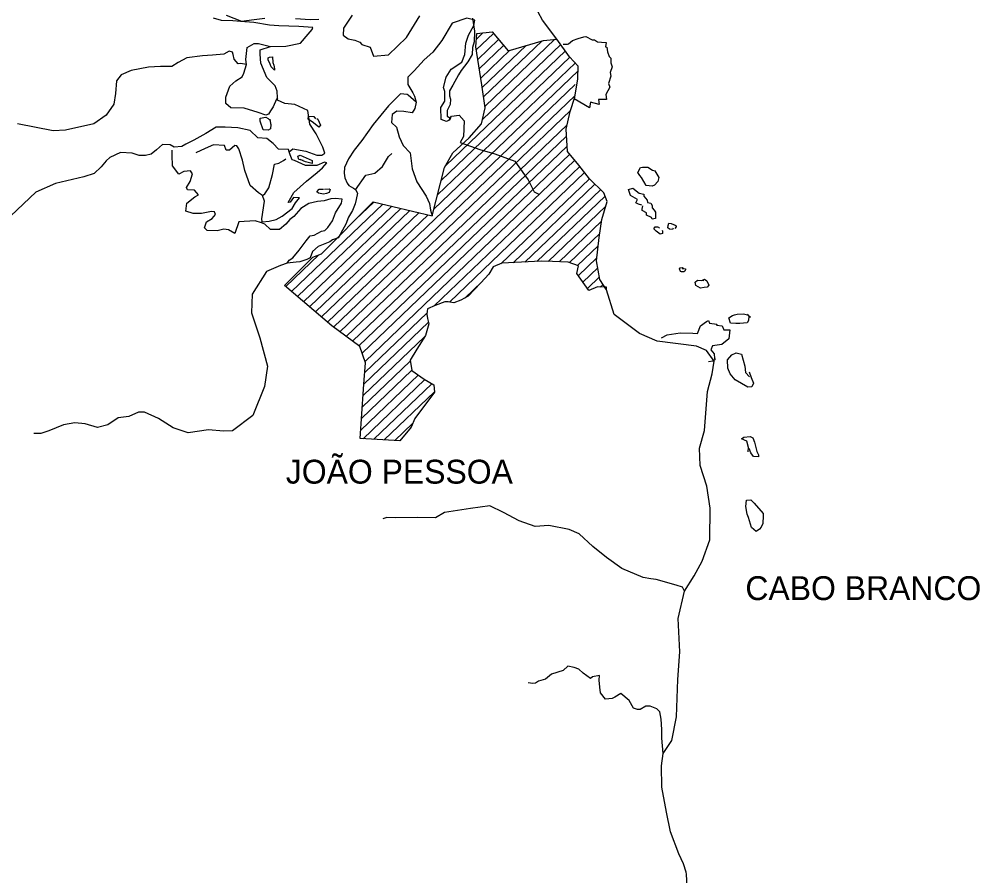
# Model space of a CAD drawing. Extents: x 662444 to 1640468, y 7452018 to 9606170.
# Drawn here: x 1612766 to 1640468, y 9181911 to 9206605 of the extents above; entities that cross this region are included whole.
import ezdxf

# ---------------------------------------------------------------- set-up
doc = ezdxf.new("R2010")
doc.units = 0
doc.layers.add('Level 1', color=7, linetype='Continuous')
doc.layers.add('Level 3', color=7, linetype='Continuous')

msp = doc.modelspace()

# ---------------------------------------------------------------- linework, layer by layer
at = {"layer": 'Level 1'}
for points in [[(1632013, 9181954), (1632000, 9182019), (1631926, 9182258), (1631789, 9182548), (1631550, 9183174), (1631430, 9183749), (1631298, 9184462), (1631293, 9185082), (1631337, 9185439), (1631591, 9185808), (1631718, 9186497), (1631761, 9187573), (1631818, 9188363), (1631767, 9189326), (1631953, 9190120), (1632234, 9190561), (1632458, 9190978), (1632680, 9191600), (1632691, 9192513), (1632598, 9193144), (1632406, 9193737), (1632389, 9194243), (1632526, 9194753), (1632617, 9195868), (1632754, 9196378), (1632806, 9196743), (1632590, 9197059), (1632302, 9197182), (1631164, 9197321), (1630653, 9197547), (1629925, 9198090), (1629704, 9198806), (1629511, 9199105), (1629414, 9199638), (1629491, 9200313), (1629564, 9200833), (1629726, 9201350), (1629628, 9201598), (1629211, 9202002), (1628908, 9202402), (1628580, 9202794), (1628535, 9203440), (1628656, 9203942), (1628789, 9204354), (1628879, 9204890), (1628890, 9205256), (1628639, 9205517), (1628275, 9206033), (1627853, 9206574), (1627478, 9207279)], [(1618739, 9206718), (1619180, 9206551), (1619546, 9206597), (1619847, 9206638)], [(1622368, 9206722), (1622122, 9206345), (1622107, 9206142), (1622257, 9206040), (1622443, 9206003), (1622586, 9205941), (1622650, 9205873), (1622890, 9205802), (1622987, 9205538), (1623417, 9205575), (1623934, 9206074), (1624318, 9206699)], [(1619756, 9200738), (1619773, 9200761), (1619975, 9200788), (1620179, 9200831), (1620352, 9200924), (1620634, 9201153), (1620729, 9201313), (1620846, 9201457), (1620677, 9201462), (1620583, 9201334), (1620518, 9201319), (1620681, 9201608), (1621047, 9201932), (1621362, 9202183), (1621512, 9202318), (1621638, 9202461), (1621574, 9202480), (1621345, 9202388), (1621020, 9202390), (1620701, 9202529), (1620637, 9202555), (1620576, 9202696), (1620547, 9202786), (1620655, 9202873), (1621033, 9202797), (1621346, 9202690), (1621491, 9202686), (1621582, 9202748), (1621522, 9202921), (1621332, 9203301), (1621146, 9203576), (1621093, 9203969), (1620718, 9204150), (1620427, 9204176), (1620219, 9204271), (1620214, 9204337), (1620204, 9204532), (1620143, 9204681), (1619908, 9204924), (1619734, 9205337), (1619718, 9205599), (1619714, 9205720), (1620008, 9205818), (1620453, 9205829), (1620877, 9205916), (1621096, 9206170), (1621213, 9206306), (1621231, 9206371), (1620827, 9206399), (1620253, 9206414), (1619986, 9206438), (1619535, 9206509), (1619147, 9206543), (1618929, 9206558), (1618598, 9206567), (1618373, 9206631)], [(1625838, 9206640), (1625892, 9206264), (1625883, 9205954), (1625838, 9205792), (1625831, 9205588), (1625703, 9205379), (1625509, 9205124), (1625432, 9205003), (1625270, 9204707), (1625175, 9204539), (1625171, 9204392), (1625200, 9204301), (1625196, 9204146), (1625110, 9203969), (1625107, 9203880), (1625105, 9203815), (1625200, 9203755), (1625165, 9203691), (1625091, 9203652), (1624931, 9203714), (1624926, 9204064), (1625045, 9204240), (1625037, 9204518), (1625000, 9204633), (1625083, 9204933), (1625227, 9205165), (1625533, 9205369), (1625620, 9205593), (1625646, 9205912), (1625727, 9206146), (1625873, 9206427), (1625910, 9206581), (1625677, 9206637), (1625252, 9206493), (1624952, 9205988), (1624699, 9205653), (1624442, 9205432), (1624157, 9205121), (1623973, 9204931), (1623970, 9204841), (1623974, 9204719), (1624059, 9204578), (1624121, 9204487), (1624166, 9204388), (1624210, 9204215), (1623981, 9204418), (1623950, 9204434), (1623764, 9204456), (1623413, 9204107), (1622976, 9203573), (1622646, 9203110), (1622427, 9202830), (1622265, 9202582), (1622144, 9202333), (1622140, 9202170), (1622159, 9202031), (1622220, 9201883), (1622274, 9201807), (1622402, 9201738), (1622465, 9201696), (1622518, 9201588), (1622481, 9201410), (1622452, 9201280), (1622382, 9201087), (1622262, 9200902), (1622183, 9200693), (1622089, 9200524), (1622020, 9200396), (1621960, 9200299), (1621796, 9200247), (1621722, 9200192), (1621533, 9200108), (1621386, 9200055), (1621228, 9199912), (1621158, 9199727), (1621059, 9199681), (1620863, 9199614), (1620749, 9199600), (1620497, 9199575), (1620549, 9199663), (1620655, 9199725), (1620841, 9199948), (1621043, 9200212), (1621161, 9200363), (1621274, 9200384), (1621481, 9200493), (1621578, 9200514), (1621670, 9200601), (1621797, 9200794), (1621885, 9201020), (1622064, 9201300), (1622084, 9201422), (1621874, 9201435), (1621752, 9201430), (1621564, 9201370), (1621369, 9201352), (1621116, 9201294)], [(1620737, 9206630), (1621156, 9206593), (1621408, 9206610)], [(1629704, 9198806), (1629706, 9198879), (1629439, 9198888), (1629193, 9198781), (1628844, 9199271), (1628892, 9199498), (1628595, 9199605), (1628150, 9199617), (1627818, 9199627), (1626683, 9199570), (1626437, 9199462), (1626309, 9199254), (1626082, 9199007), (1625899, 9198809), (1625715, 9198619), (1625500, 9198502), (1625303, 9198427), (1625135, 9198455), (1625037, 9198459), (1624759, 9198353), (1624537, 9198253), (1624524, 9198106), (1624545, 9197975), (1624581, 9197820), (1624481, 9197487), (1624234, 9197095), (1624038, 9196775), (1624093, 9196479), (1624442, 9196232), (1624720, 9196062), (1624747, 9195857), (1624172, 9195098), (1624068, 9194841), (1623747, 9194451), (1622600, 9194516), (1622693, 9195940), (1622706, 9196087), (1622757, 9196697), (1622585, 9197174), (1621777, 9197769), (1620412, 9198933), (1621231, 9199749), (1621485, 9199840), (1622972, 9201339), (1624676, 9200940), (1625035, 9202332), (1625275, 9202749), (1625741, 9203185), (1626094, 9203591), (1626205, 9204052), (1626103, 9204716), (1625934, 9205806), (1625963, 9206196), (1626410, 9206240), (1626863, 9205697), (1627884, 9205995), (1628275, 9206033)], [(1625948, 9205719), (1626446, 9206196)], [(1625951, 9206033), (1626140, 9206213)], [(1620214, 9204337), (1620181, 9204305), (1620093, 9204079), (1620016, 9203967), (1619957, 9203871), (1619882, 9203840), (1619658, 9203912), (1619257, 9204038), (1618869, 9204048), (1618720, 9204175), (1618725, 9204354), (1618839, 9204677), (1619014, 9204827), (1619196, 9204944), (1619248, 9205048), (1619320, 9205300), (1619301, 9205447), (1619343, 9205788), (1619540, 9205905), (1619663, 9205901), (1620008, 9205818)], [(1625989, 9205448), (1626590, 9206024)], [(1626032, 9205178), (1626735, 9205851)], [(1626115, 9204636), (1627382, 9205849)], [(1626124, 9203711), (1628384, 9205877)], [(1626157, 9204365), (1627848, 9205985)], [(1626199, 9204095), (1628217, 9206027)], [(1628456, 9205889), (1628578, 9205885), (1628610, 9205893), (1628727, 9205996), (1628882, 9206048), (1629046, 9206101), (1629111, 9206106), (1629286, 9206012), (1629359, 9206010), (1629446, 9205950), (1629560, 9205947), (1629696, 9205935), (1629677, 9205805), (1629717, 9205796), (1629736, 9205664), (1629782, 9205533), (1629829, 9205483), (1629825, 9205345), (1629869, 9205229), (1629807, 9205067), (1629829, 9204960), (1629758, 9204751), (1629795, 9204643), (1629683, 9204434), (1629703, 9204287), (1629468, 9204294), (1629487, 9204147), (1629246, 9204210), (1629209, 9204048), (1628775, 9204309)], [(1619320, 9205300), (1619143, 9205329), (1619078, 9205323), (1618961, 9205457), (1618940, 9205588), (1618918, 9205653), (1618822, 9205680), (1618665, 9205595), (1618341, 9205571), (1618056, 9205547), (1617601, 9205494), (1617347, 9205355), (1617165, 9205246), (1616840, 9205239), (1616492, 9205224), (1615995, 9205124), (1615708, 9205001), (1615573, 9204826), (1615538, 9204468), (1615497, 9204159), (1615269, 9203840), (1614921, 9203589), (1614105, 9203408), (1613749, 9203386), (1612718, 9203586)], [(1625068, 9202390), (1628516, 9205691)], [(1626074, 9204907), (1626915, 9205712)], [(1619948, 9205436), (1619950, 9205494), (1619983, 9205509), (1620072, 9205522), (1620083, 9205359), (1620112, 9205277), (1620126, 9205171), (1620125, 9205138), (1620031, 9205230), (1620001, 9205313), (1619948, 9205436)], [(1624832, 9201541), (1628804, 9205346)], [(1624937, 9201954), (1628648, 9205508)], [(1624725, 9201129), (1628886, 9205114)], [(1621652, 9197876), (1628803, 9204723)], [(1621827, 9197731), (1628799, 9204408)], [(1624210, 9204215), (1624172, 9204036), (1624103, 9203909), (1623854, 9203948), (1623660, 9203953), (1623519, 9203860), (1623503, 9203632), (1623645, 9203497), (1623725, 9203217), (1623840, 9202962), (1624036, 9202752), (1624102, 9202294), (1624236, 9201914), (1624500, 9201500), (1624598, 9201293), (1624624, 9201096), (1624674, 9200940)], [(1622010, 9197597), (1628665, 9203969)], [(1619993, 9203723), (1620013, 9203600), (1620020, 9203567), (1620016, 9203445), (1619942, 9203406), (1619806, 9203418), (1619716, 9203666), (1619718, 9203756), (1619881, 9203784), (1619944, 9203741), (1620000, 9203682)], [(1621345, 9203741), (1621377, 9203725), (1621453, 9203551), (1621410, 9203495), (1621253, 9203614), (1621101, 9203724), (1621104, 9203806), (1621258, 9203802), (1621312, 9203734)], [(1625165, 9203691), (1625234, 9203811), (1625453, 9203837), (1625595, 9203678), (1625580, 9203222), (1625487, 9203054), (1626054, 9202850), (1626480, 9202724), (1627057, 9202511), (1627336, 9202120), (1627445, 9201978), (1627621, 9201630), (1627756, 9201561)], [(1620547, 9202786), (1620532, 9202852), (1620241, 9202859), (1620093, 9203019), (1619911, 9203171), (1619645, 9203187), (1619424, 9203396), (1619070, 9203472), (1618707, 9203491), (1618448, 9203489), (1618150, 9203311), (1617805, 9203116), (1617574, 9203001), (1617451, 9202939), (1617239, 9202921), (1617120, 9202981), (1616902, 9202996), (1616727, 9202837), (1616570, 9202711), (1616406, 9202675), (1616228, 9202680), (1616027, 9202743), (1615688, 9202761), (1615377, 9202623), (1615269, 9202519), (1615134, 9202352), (1614925, 9202154), (1614631, 9202064), (1613815, 9201867), (1613241, 9201615), (1612524, 9200934)], [(1622195, 9197462), (1628564, 9203563)], [(1622378, 9197327), (1628549, 9203237)], [(1621116, 9201294), (1620885, 9201145), (1620684, 9200915), (1620568, 9200829), (1620459, 9200701), (1620276, 9200543), (1620008, 9200542), (1619851, 9200694), (1619756, 9200738), (1619571, 9200791), (1619101, 9200764), (1618985, 9200424), (1618802, 9200536), (1618665, 9200556), (1618477, 9200504), (1618186, 9200513), (1618108, 9200589), (1618170, 9200766), (1618326, 9200859), (1618427, 9200979), (1618397, 9201053), (1618308, 9201064), (1618023, 9201007), (1617781, 9201006), (1617572, 9201069), (1617603, 9201304), (1617835, 9201485), (1617935, 9201547), (1617824, 9201673), (1617623, 9201686), (1617593, 9201752), (1617695, 9201929), (1617759, 9202147), (1617704, 9202238), (1617510, 9202212), (1617369, 9202142), (1617190, 9202375), (1617176, 9202685), (1617180, 9202832)], [(1619773, 9200761), (1619767, 9200851), (1619839, 9201362), (1619780, 9201520), (1619668, 9201596), (1619424, 9201815), (1619275, 9202243), (1619203, 9202539), (1619100, 9202868), (1619038, 9202959), (1618981, 9202961), (1618831, 9202826), (1618735, 9202830), (1618682, 9202961), (1618367, 9202986), (1618129, 9202879), (1617858, 9202756)], [(1622561, 9197192), (1628570, 9202946)], [(1619780, 9201520), (1619846, 9201574), (1619964, 9201742), (1620066, 9202131), (1620130, 9202423), (1620253, 9202451), (1620385, 9202529), (1620451, 9202576)], [(1620952, 9202529), (1620831, 9202558), (1620802, 9202656), (1620868, 9202687), (1621219, 9202530), (1621217, 9202449), (1621024, 9202495), (1620871, 9202557)], [(1622468, 9201689), (1622761, 9202112), (1623021, 9202169), (1623247, 9202359), (1623417, 9202648), (1623508, 9202735)], [(1622657, 9196973), (1628649, 9202712)], [(1622741, 9196742), (1628793, 9202539)], [(1624736, 9198343), (1628936, 9202364)], [(1630663, 9202099), (1630602, 9202182), (1630679, 9202334), (1630737, 9202341), (1630898, 9202336), (1631025, 9202251), (1631098, 9202233), (1631212, 9202042), (1631185, 9201929), (1631085, 9201825), (1631020, 9201794), (1630849, 9201808), (1630711, 9202040), (1630663, 9202099)], [(1625171, 9198449), (1629072, 9202185)], [(1626653, 9199557), (1629209, 9202004)], [(1621574, 9201705), (1621704, 9201718), (1621737, 9201700), (1621709, 9201611), (1621627, 9201581), (1621537, 9201560), (1621401, 9201587), (1621346, 9201630), (1621413, 9201709), (1621543, 9201705)], [(1627009, 9199586), (1629370, 9201848)], [(1627351, 9199603), (1629532, 9201691)], [(1630719, 9201248), (1630622, 9201276), (1630551, 9201310), (1630595, 9201407), (1630395, 9201519), (1630336, 9201700), (1630466, 9201737), (1630648, 9201594), (1630776, 9201557), (1630775, 9201500), (1630877, 9201391), (1630883, 9201318), (1630980, 9201306), (1631018, 9201231), (1631024, 9201166), (1631078, 9201100), (1631117, 9201042), (1631113, 9200919), (1631112, 9200862), (1631022, 9200840), (1630999, 9200890), (1630855, 9200959), (1630858, 9201025), (1630730, 9201093), (1630731, 9201126), (1630750, 9201223)], [(1627694, 9199621), (1629664, 9201508)], [(1620623, 9198753), (1623253, 9201273)], [(1620794, 9198607), (1623514, 9201213)], [(1620966, 9198460), (1623775, 9201151)], [(1622475, 9200838), (1622993, 9201334)], [(1628018, 9199621), (1629684, 9201216)], [(1621138, 9198314), (1624035, 9201090)], [(1621310, 9198167), (1624296, 9201029)], [(1621480, 9198022), (1624556, 9200967)], [(1628334, 9199612), (1629557, 9200783)], [(1631304, 9200522), (1631319, 9200497), (1631317, 9200432), (1631251, 9200410), (1631133, 9200494), (1631071, 9200562), (1631104, 9200617), (1631169, 9200616), (1631201, 9200615), (1631233, 9200582)], [(1631621, 9200579), (1631604, 9200547), (1631524, 9200548), (1631476, 9200591), (1631478, 9200656), (1631504, 9200721), (1631569, 9200718), (1631681, 9200666), (1631712, 9200649), (1631711, 9200616), (1631678, 9200576)], [(1628636, 9199591), (1629507, 9200425)], [(1628871, 9199506), (1629463, 9200072)], [(1620451, 9198900), (1621402, 9199811)], [(1620497, 9199575), (1620301, 9199507), (1619898, 9199331), (1619482, 9198674), (1619465, 9198136), (1619702, 9197420), (1619928, 9196607), (1619837, 9196014), (1619504, 9195183), (1618916, 9194736), (1618657, 9194726), (1618228, 9194771), (1617643, 9194682), (1617202, 9194826), (1616782, 9195098), (1616382, 9195273), (1616204, 9195278), (1615925, 9195155), (1615616, 9195115), (1615319, 9194911), (1615025, 9194830), (1614672, 9194938), (1614366, 9194972), (1614040, 9194915), (1613622, 9194740), (1613393, 9194664), (1613183, 9194662)], [(1628887, 9199210), (1629424, 9199724)], [(1629019, 9199025), (1629450, 9199439)], [(1631886, 9199420), (1631982, 9199410), (1631981, 9199377), (1631964, 9199346), (1631931, 9199322), (1631866, 9199323), (1631834, 9199333), (1631812, 9199406), (1631829, 9199439), (1631894, 9199445), (1631926, 9199420)], [(1625619, 9198567), (1626105, 9199032)], [(1629151, 9198840), (1629499, 9199174)], [(1629522, 9198885), (1629603, 9198962)], [(1632449, 9199070), (1632532, 9199108), (1632595, 9199066), (1632656, 9198942), (1632605, 9198879), (1632524, 9198873), (1632410, 9198852), (1632275, 9198929), (1632262, 9199027), (1632328, 9199081), (1632506, 9199076)], [(1622734, 9196425), (1624527, 9198142)], [(1633764, 9198102), (1633803, 9198044), (1633799, 9197922), (1633756, 9197850), (1633544, 9197832), (1633431, 9197834), (1633278, 9197839), (1633234, 9197995), (1633333, 9198066), (1633399, 9198080), (1633472, 9198103), (1633643, 9198114), (1633779, 9198086), (1633858, 9198018)], [(1622706, 9196088), (1624569, 9197872)], [(1631289, 9197415), (1631454, 9197508), (1631827, 9197563), (1632192, 9197552), (1632330, 9197548), (1632418, 9197766), (1632583, 9197892), (1632649, 9197915), (1632678, 9197840), (1632880, 9197818), (1632879, 9197785), (1633040, 9197765), (1633086, 9197649), (1633255, 9197652), (1633232, 9197392), (1633033, 9197227), (1632764, 9197186), (1632712, 9197072), (1632806, 9196955), (1632817, 9196825), (1632832, 9196792), (1632766, 9196745), (1632645, 9196732)], [(1622681, 9195753), (1624465, 9197462)], [(1633817, 9196437), (1633878, 9196280), (1633946, 9196115), (1633893, 9196011), (1633779, 9195998), (1633414, 9196212), (1633265, 9196379), (1633206, 9196544), (1633197, 9196781), (1633315, 9196933), (1633438, 9196986), (1633599, 9196949), (1633693, 9196604), (1633711, 9196416), (1633830, 9196298)], [(1622659, 9195421), (1624043, 9196747)], [(1622638, 9195090), (1624092, 9196483)], [(1622616, 9194758), (1624278, 9196350)], [(1622682, 9194512), (1624466, 9196218)], [(1622989, 9194494), (1624663, 9196097)], [(1623295, 9194477), (1624746, 9195866)], [(1623602, 9194459), (1624111, 9194947)], [(1633787, 9194137), (1633799, 9194259), (1633748, 9194440), (1633596, 9194510), (1633662, 9194557), (1633848, 9194576), (1633920, 9194533), (1633974, 9194409), (1634038, 9194138), (1634091, 9194047), (1634090, 9193990), (1633944, 9193994), (1633867, 9194103), (1633814, 9194226)], [(1631953, 9190120), (1631898, 9190232), (1631708, 9190290), (1631138, 9190454), (1630985, 9190474), (1630759, 9190514), (1630143, 9190768), (1629699, 9191083), (1629313, 9191404), (1628919, 9191765), (1628624, 9191897), (1628044, 9192011), (1627646, 9191981), (1627182, 9192142), (1626737, 9192383), (1626337, 9192574), (1625777, 9192501), (1625028, 9192383), (1624772, 9192228), (1624262, 9192242), (1623606, 9192228), (1623364, 9192236), (1623250, 9192206)], [(1633759, 9192340), (1633721, 9192558), (1633743, 9192736), (1633864, 9192748), (1633959, 9192656), (1634217, 9192355), (1634223, 9192289), (1634216, 9192069), (1634164, 9191957), (1634113, 9191901), (1634023, 9191839), (1633889, 9191949), (1633800, 9192236), (1633759, 9192340)], [(1631337, 9185439), (1631295, 9185874), (1631294, 9186127), (1631279, 9186428), (1631237, 9186633), (1631159, 9186725), (1630959, 9186797), (1630838, 9186800), (1630673, 9186707), (1630600, 9186701), (1630480, 9186745), (1630357, 9186961), (1630112, 9187163), (1629947, 9187062), (1629865, 9187024), (1629670, 9187005), (1629530, 9187189), (1629511, 9187352), (1629493, 9187549), (1629497, 9187687), (1629301, 9187644), (1629243, 9187596), (1629030, 9187749), (1628903, 9187868), (1628775, 9187920), (1628590, 9187950), (1628449, 9187832), (1628121, 9187719), (1627939, 9187577), (1627743, 9187518), (1627660, 9187462), (1627579, 9187458), (1627442, 9187477)], [(1632030, 9181587), (1632013, 9181954)]]:
    msp.add_lwpolyline(points, dxfattribs=at)

# ---------------------------------------------------------------- texts
at = {"layer": 'Level 3'}
for s, height, p in [('JOÃO PESSOA', 688.31, (1620455, 9193217)), ('CABO BRANCO', 688.53, (1633708, 9189859))]:
    msp.add_text(s, height=height, dxfattribs=at).set_placement(p)

doc.saveas('drawing.dxf')
